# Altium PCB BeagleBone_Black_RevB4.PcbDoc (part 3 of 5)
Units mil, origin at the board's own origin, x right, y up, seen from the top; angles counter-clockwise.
Board outline 3401 x 2151 mil, 6 copper layers (TOP, LYR2_GND, LYR3, LYR4, LYR5_PWR, BOTTOM), stack 62 mil thick; 381 components, 310 nets, 1705 pads, 850 vias.
Unrouted connection lines stored in the file: 1.
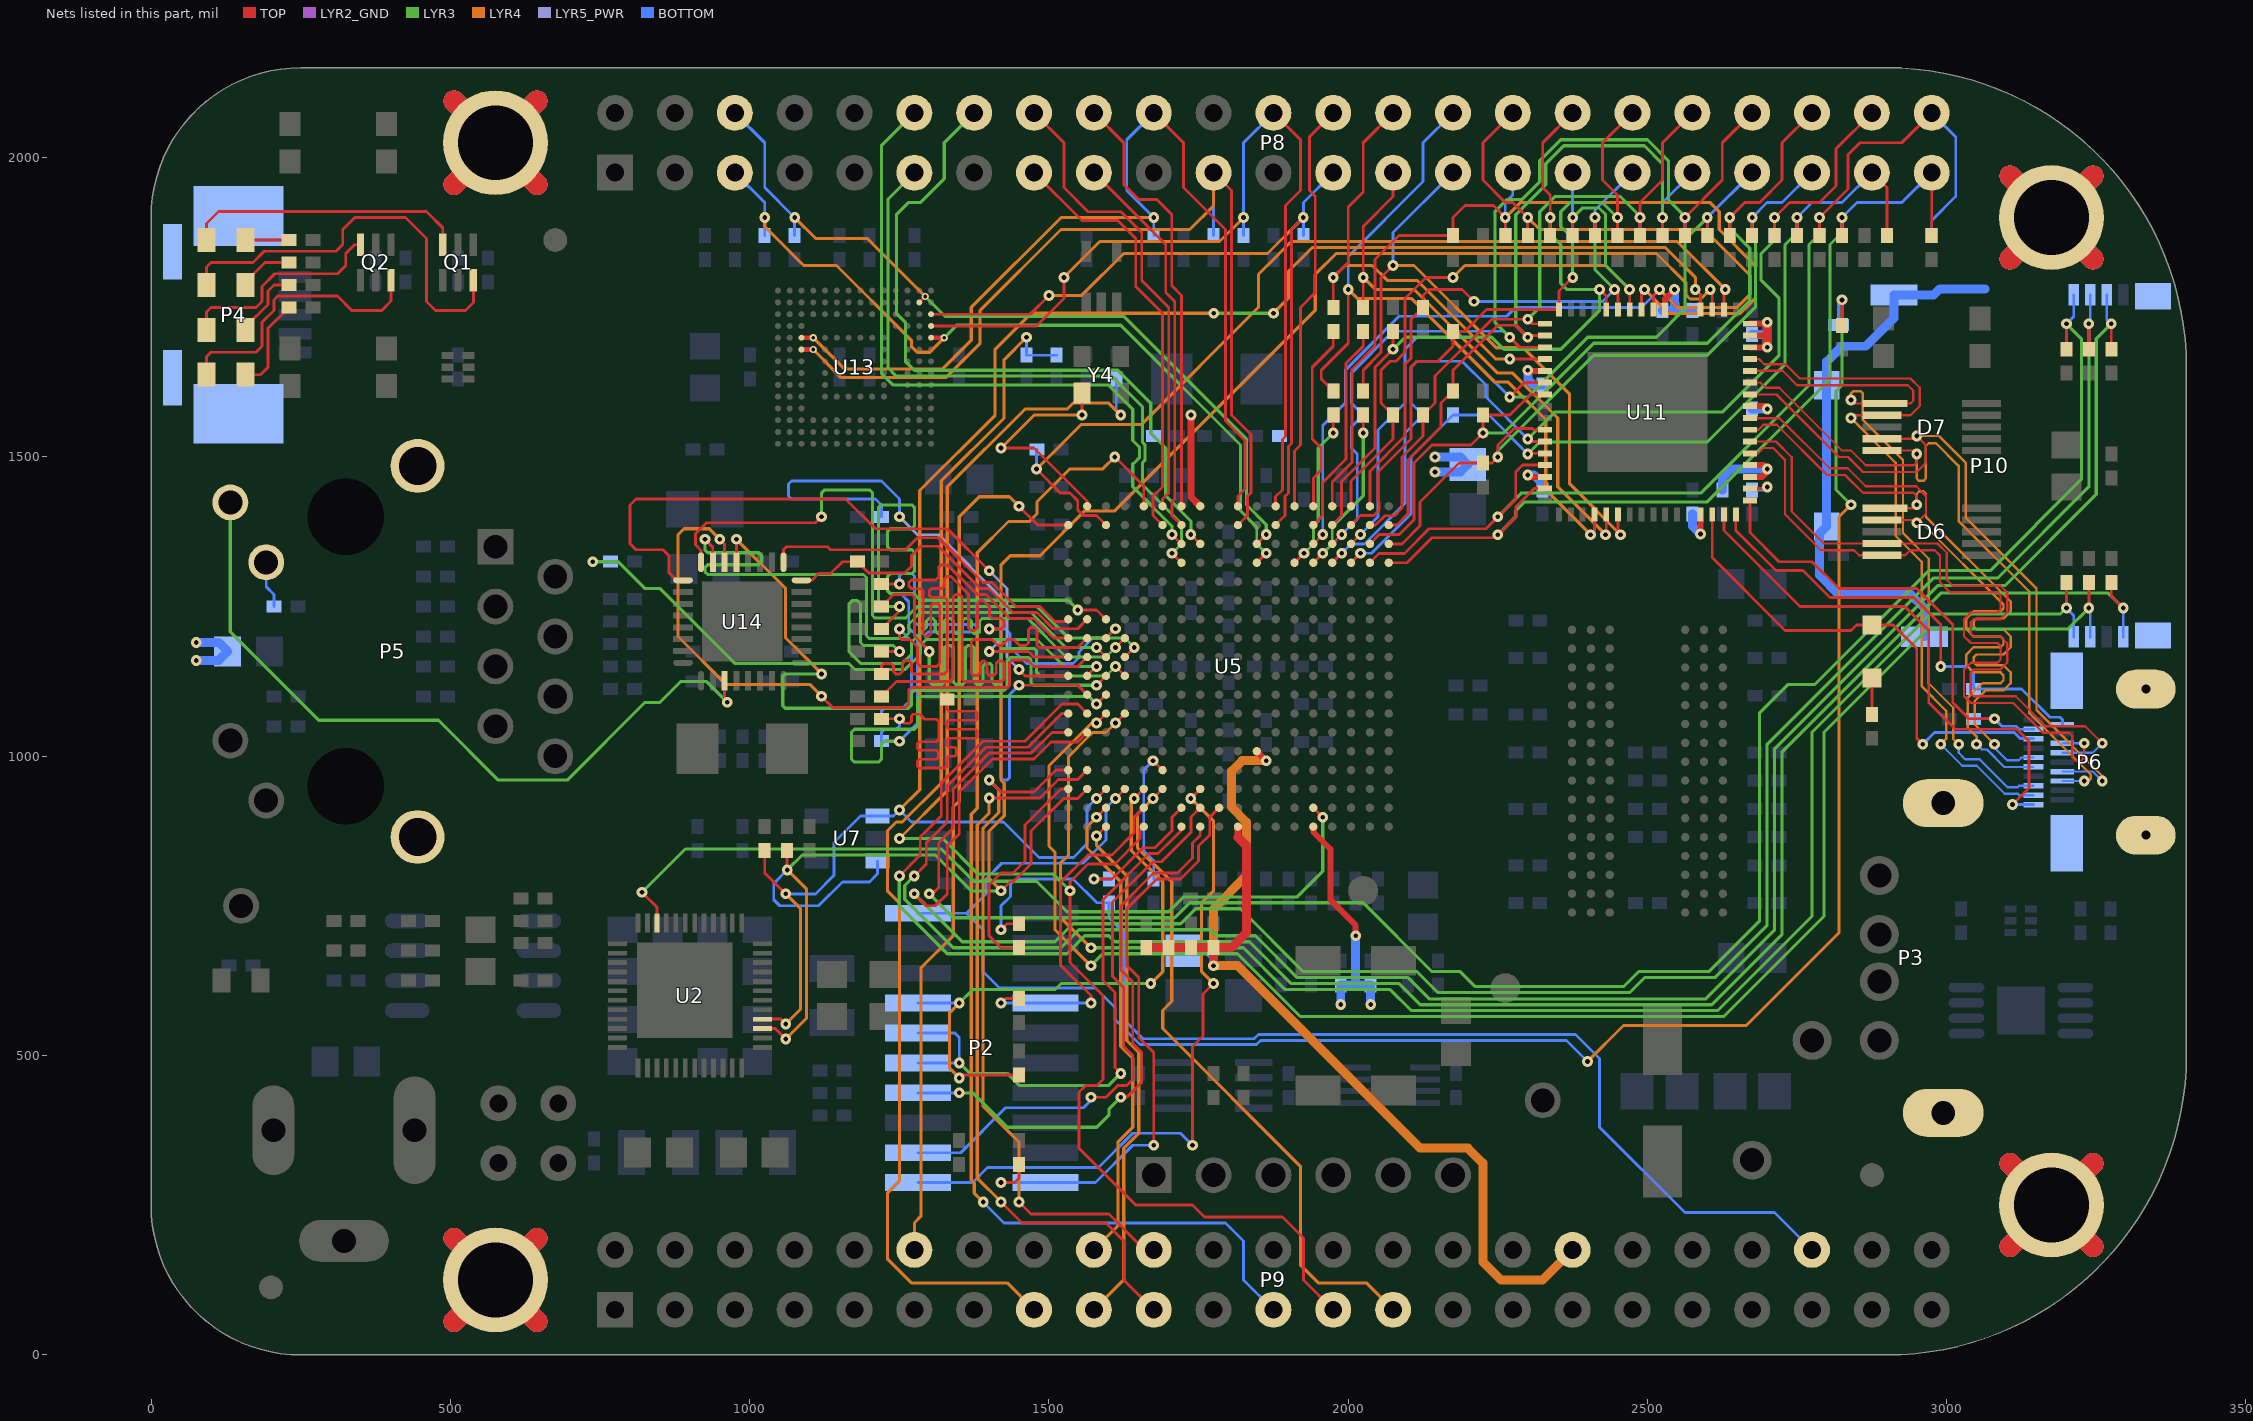
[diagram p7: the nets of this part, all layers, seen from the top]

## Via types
v1: diameter 18, hole 8, TOP to BOTTOM, tented both sides, 793 vias
v2: diameter 22, hole 12, TOP to BOTTOM, tented both sides, 30 vias
v3: diameter 12, hole 6, TOP to BOTTOM, tented both sides, 27 vias

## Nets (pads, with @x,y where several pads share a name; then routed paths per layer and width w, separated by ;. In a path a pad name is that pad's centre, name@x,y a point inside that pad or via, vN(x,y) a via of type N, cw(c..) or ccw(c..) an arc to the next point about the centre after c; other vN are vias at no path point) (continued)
GND_EARTH: MTG1.1 MTG2.1 MTG3.1 MTG4.1 P3.5 P3.6 P4.6 P4.7 P4.8 P4.9 P5.13 P5.14 P6.20 P6.21 P6.22 P6.23 P10.11 P10.12 P10.13 P10.14 P10.15 P10.16 R136.2 | length 7357.1
  TOP w35: 505.46,55.46 MTG1.1@575,125 ; 505.46,194.54 MTG1.1@575,125 ; 505.46,1955.46 MTG3.1@575,2025 ; 505.46,2094.54 MTG3.1@575,2025 ; 644.54,55.46 MTG1.1@575,125 ; 644.54,194.54 MTG1.1@575,125 ; 644.54,1955.46 MTG3.1@575,2025 ; 644.54,2094.54 MTG3.1@575,2025 ; 3105.46,180.46 MTG2.1@3175,250 ; 3105.46,319.54 MTG2.1@3175,250 ; 3105.46,1830.46 MTG4.1@3175,1900 ; 3105.46,1969.54 MTG4.1@3175,1900 ; 3244.54,180.46 MTG2.1@3175,250 ; 3244.54,319.54 MTG2.1@3175,250 ; 3244.54,1830.46 MTG4.1@3175,1900 ; 3244.54,1969.54 MTG4.1@3175,1900
  LYR2_GND w35: 505.46,55.46 MTG1.1@575,125 ; 505.46,194.54 MTG1.1@575,125 ; 505.46,1955.46 MTG3.1@575,2025 ; 505.46,2094.54 MTG3.1@575,2025 ; 644.54,55.46 MTG1.1@575,125 ; 644.54,194.54 MTG1.1@575,125 ; 644.54,1955.46 MTG3.1@575,2025 ; 644.54,2094.54 MTG3.1@575,2025 ; 3105.46,180.46 MTG2.1@3175,250 ; 3105.46,319.54 MTG2.1@3175,250 ; 3105.46,1830.46 MTG4.1@3175,1900 ; 3105.46,1969.54 MTG4.1@3175,1900 ; 3244.54,180.46 MTG2.1@3175,250 ; 3244.54,319.54 MTG2.1@3175,250 ; 3244.54,1830.46 MTG4.1@3175,1900 ; 3244.54,1969.54 MTG4.1@3175,1900
  LYR5_PWR w35: 505.46,55.46 MTG1.1@575,125 ; 505.46,194.54 MTG1.1@575,125 ; 505.46,1955.46 MTG3.1@575,2025 ; 505.46,2094.54 MTG3.1@575,2025 ; 644.54,55.46 MTG1.1@575,125 ; 644.54,194.54 MTG1.1@575,125 ; 644.54,1955.46 MTG3.1@575,2025 ; 644.54,2094.54 MTG3.1@575,2025 ; 3105.46,180.46 MTG2.1@3175,250 ; 3105.46,319.54 MTG2.1@3175,250 ; 3105.46,1830.46 MTG4.1@3175,1900 ; 3105.46,1969.54 MTG4.1@3175,1900 ; 3244.54,180.46 MTG2.1@3175,250 ; 3244.54,319.54 MTG2.1@3175,250 ; 3244.54,1830.46 MTG4.1@3175,1900 ; 3244.54,1969.54 MTG4.1@3175,1900
  BOTTOM w15: v1(75,1160) 112.5,1160 R136.2@127.5,1175 112.5,1190 v1(75,1190) ; P10.12@2963,1199.57 2963,1247 2940,1270 2820,1270 2787.5,1302.5 2787.5,1372.5 2798.63,1383.63 P10.16@2799.5,1383.63 P10.15@2799.5,1619.84 2799.5,1659.5 2825,1685 2864.66,1685 2911.82,1732.16 P10.11@2911.82,1770.43 2977.93,1770.43 2988.54,1781.04 3063.96,1781.04
  BOTTOM w35: 505.46,55.46 MTG1.1@575,125 ; 505.46,194.54 MTG1.1@575,125 ; 505.46,1955.46 MTG3.1@575,2025 ; 505.46,2094.54 MTG3.1@575,2025 ; 644.54,55.46 MTG1.1@575,125 ; 644.54,194.54 MTG1.1@575,125 ; 644.54,1955.46 MTG3.1@575,2025 ; 644.54,2094.54 MTG3.1@575,2025 ; 3105.46,180.46 MTG2.1@3175,250 ; 3105.46,319.54 MTG2.1@3175,250 ; 3105.46,1830.46 MTG4.1@3175,1900 ; 3105.46,1969.54 MTG4.1@3175,1900 ; 3244.54,180.46 MTG2.1@3175,250 ; 3244.54,319.54 MTG2.1@3175,250 ; 3244.54,1830.46 MTG4.1@3175,1900 ; 3244.54,1969.54 MTG4.1@3175,1900
GND_OSC0: C25.2 C26.2 U5.V11 | length 158.6
  TOP w12: v1(1737.5,1570) 1737.5,1432.98 U5.V11@1752.76,1417.72
GND_OSC1: C21.1 C22.1 U5.A5 | length 409.1
  TOP w10: U5.A5@1941.73,882.28 1941.73,873.27 1970,845 1970,760 2012.5,717.5 v1(2012.5,700)
  BOTTOM w15: v1(1987.5,585) C21.1@1987.5,617.5 2012.5,617.5 ; v1(2012.5,700) 2012.5,617.5 ; v1(2037.5,585) C22.1@2037.5,617.5 2012.5,617.5
GNDA_ADC: C31.2 C32.2 C33.2 C93.2 FB3.1 P9.34 U5.A9 U5.E8 | length 1840.7
  TOP w10: U5.E8@1847.24,1008.27 v1(1862.99,992.52)
  TOP w12: 1815.75,865 U5.A9@1815.75,882.28
  TOP w15: C32.2@1662.5,680 C31.2@1700,680 C33.2@1737.5,680 C93.2@1775,680 ; v1(1775,650) C93.2@1775,680 ; 1815.75,865 1815.75,864.25 1830,850 1830,705 1805,680 C93.2@1775,680
  LYR4 w15: v1(1862.99,992.52) 1822.52,992.52 1805,975 1805,915 1830,890 1830,800 1775,745 v1(1775,650) 1815,650 2120,345 2200,345 2225,320 2225,155 2255,125 2325,125 P9.34@2375,175
  BOTTOM w15: FB3.1@1725,674.9 1765.25,674.9 1775,665.15 v1(1775,650)
GPIO0_7: P9.42 R50.1 R51.1 | length 1889.3
  TOP w4.75: v1(1420,710) 1430,720 R50.1@1450,720
  BOTTOM w4.75: v1(1420,710) 1420,750 1435.74,765.74 1435.74,785.74 1445,795 1540,795 1580,755 R51.1@1600,755 1600,730 1625,705 1625,560 1657.25,527.75 1842.75,527.75 1850,535 2380,535 2420,495 2420,380 2562.5,237.5 2712.5,237.5 P9.42@2775,175
GPIO0_7SRC: R50.2 U5.C18 | length 377.1
  TOP w4.75: R50.2@1450,680 1420,680 1400,700 1400,785 1419.62,804.62 1439.62,804.62 1460,825 1460,885 1520.28,945.28 U5.C18@1532.28,945.28
GPIO0_26: P8.14 U5.T11 | length 1195.3
  TOP w4.75: v1(1737,1370.5) U5.T11@1752.76,1354.72
  LYR3 w5.25: P8.14@1375,2075 1325,2025 1325,1965 1285,1925 1265,1925 1245,1905 1245,1740 1260,1725 1260,1660 1275,1645 1615,1645 1670,1590 1670,1540 1695,1515 1695,1435 1737,1393 v1(1737,1370.5)
GPIO0_27: P8.17 U5.U12 | length 653
  TOP w4.75: P8.17@1575,1975 1695,1855 1695,1775 1710,1760 1710,1430 1705.63,1425.63 1705.63,1401.85 U5.U12@1721.26,1386.22
GPIO1_12: P8.12 U5.T12 | length 1171.6
  TOP w4.75: v1(1705.5,1370.5) U5.T12@1721.26,1354.72
  LYR3 w5.25: P8.12@1275,2075 1220,2020 1220,1640 1240,1620 1600,1620 1640,1580 1640,1527.61 1650.99,1516.62 1650.99,1498.38 1641.62,1489.01 1640,1489.01 1640,1450 1705.5,1384.5 v1(1705.5,1370.5)
GPIO1_13: P8.11 U5.R12 | length 1100.4
  TOP w4.75: v1(1705.5,1339) U5.R12@1721.26,1323.23
  LYR3 w4.75: v1(1705.5,1339) 1721.26,1354.76 1721.26,1388.74
  LYR3 w5.25: P8.11@1275,1975 1230.91,1930.91 1230.91,1649.09 1245,1635 1605,1635 1656.26,1583.74 1656.26,1524.44 1660.24,1520.46 1660.24,1494.54 1656.26,1490.56 1656.26,1453.74 1721.26,1388.74
GPIO1_14: P8.16 U5.V13 | length 786.9
  TOP w4.75: P8.16@1475,2075 1525,2025 1525,1950 1565.25,1909.75 1620.25,1909.75 1655,1875 1655,1795 1700,1750 1700,1440 1689.76,1429.76 U5.V13@1689.76,1417.72
GPIO1_15: P8.15 U5.U13 | length 725.9
  TOP w4.75: P8.15@1475,1975 1555,1895 1615,1895 1645,1865 1645,1785 1689.74,1740.26 1689.74,1450 1674.03,1434.29 1674.03,1401.95 U5.U13@1689.76,1386.22
GPIO1_16: P9.15 R160.2 R161.2 | length 2018.9
  LYR4 w5.25: v1(1462.5,1700) 1425,1662.5 1425,1565 1320,1460 1320,955 1255,890 1245,890 1230,875 1230,775 1250,755 1250,290 1230,270 1230,160 1270,120 1430,120 P9.15@1475,75
  BOTTOM w4.75: v1(1462.5,1700) R161.2@1462.5,1670 R160.2@1512.5,1670
GPIO1_17: P9.23 U5.V14 | length 2105.3
  TOP w4.75: v1(1610,1500) 1658.27,1451.73 U5.V14@1658.27,1417.72
  LYR4 w5.25: v1(1390,255) 1375,270 1375,286.91 1370,291.91 1370,903.09 1380,913.09 1380,1340 1432.26,1392.26 1467.26,1392.26 1480,1405 1480,1425 1535,1480 1590,1480 v1(1610,1500)
  BOTTOM w4.75: v1(1390,255) 1425,220 1795,220 1825,190 1825,125 P9.23@1875,75
GPIO1_28: P9.12 U5.U18 | length 1471.8
  TOP w4.75: v1(1450,1417.5) 1481.28,1386.22 U5.U18@1532.28,1386.22
  LYR4 w5.25: P9.12@1275,175 1275,220 1285.99,230.99 1285.99,645.99 1340,700 1340,915 1350,925 1350,1400 1383.49,1433.49 1434.01,1433.49 v1(1450,1417.5)
GPIO1_29: P8.26 U5.V6 | length 692.4
  TOP w4.75: U5.V6@1910.24,1417.72 1910.24,1510.24 1920,1520 1920,1750 1945,1775 1945,1935 1935,1945 1935,2035 P8.26@1975,2075
GPIO2_1: P8.18 U5.V12 | length 735.4
  TOP w4.75: P8.18@1575,2075 1625,2025 1625,1955 1650,1930 1680,1930 1705,1905 1705,1786.26 1721.26,1770 U5.V12@1721.26,1417.72
GPIO3_18: R51.2 U5.B12 | length 233.7
  TOP w4.75: v1(1575,795) 1605,795 1657.12,847.12 1677.12,847.12 1705.39,875.39 1705.39,897.91 U5.B12@1721.26,913.78
  BOTTOM w4.75: v1(1575,795) R51.2@1600,795
GPIO3_19: P9.27 U5.C13 | length 1123.9
  TOP w4.75: v1(1674,929.5) U5.C13@1689.76,945.28
  LYR4 w5.25: v1(1674,929.5) 1647.76,903.26 1647.76,847.24 1705,790 1705,590 1690,575 1690,545 1920,315 1920,150 1950,120 2030,120 P9.27@2075,75
GPIO3_20: R20.2 U5.D13 | length 233.2
  TOP w4.75: v1(1674,992.5) U5.D13@1689.73,976.77
  BOTTOM w4.75: v1(1674,992.5) 1658.26,976.76 1658.26,841.74 1675,825 R20.2@1675,795
GPIO3_21: P9.25 R167.2 U5.A14 | length 2603.7
  TOP w4.75: U5.A14@1658.27,882.28 1652.25,876.26 1652.25,862.25 1610,820 1565,820 1535,790 v1(1535,775) 1535,655 1590,600 1590,460 1580,450 1561.38,450 1550,438.62 1550,345 1645,250 1740,250 1760,230 1890,230 1925,195 1925,125 P9.25@1975,75
  LYR3 w5.25: v1(1250.25,862.5) 1322.5,862.5 1382,803 1507,803 v1(1535,775)
  LYR4 w5.25: v1(1250.25,862.5) 1330,942.25 1330,1450 1460,1580 1530,1580 1540,1590 1600,1590 v1(1620,1570)
  BOTTOM w4.75: R167.2@1612.5,1630 1612.5,1577.5 v1(1620,1570)
GRN_C: P5.10 R132.2 | length 79.4
  BOTTOM w4.75: P5.10@192,1324 192,1283 205,1270 R132.2@205,1250
GRNA: P5.9 U14.3 | length 1270
  TOP w4.75: U14.3@957.95,1126 957.95,1094.55 v1(962.5,1090)
  LYR3 w5.25: P5.9@132,1424 132,1208 280,1060 480,1060 580,960 695,960 825,1090 850,1090 885,1125 927.5,1125 v1(962.5,1090)
HDMI_1V8: C144.1 C145.1 C146.1 C147.1 C148.1 C149.1 C150.1 C151.1 FB5.1 U11.5 U11.14 U11.29 U11.35 U11.36 U11.41 U11.46 U11.47 U11.48 U11.55 | length 882.9
  TOP w10: v1(2300,1470) 2303.27,1466.73 U11.14@2328.74,1466.73 ; v1(2300,1645) 2301.1,1643.9 U11.5@2328.74,1643.9 ; U11.55@2529.53,1746.26 2529.53,1763.56 2545,1779.03 v1(2545,1780) ; v1(2588.58,1371.42) U11.29@2588.58,1403.74 ; U11.35@2671.26,1466.73 2691.73,1466.73 2700,1475 v1(2700,1480) 2693.58,1486.42 U11.36@2671.26,1486.42 ; U11.41@2671.26,1584.84 2695.16,1584.84 v1(2700,1580) ; U11.46@2671.26,1683.27 v1(2700,1683.27) ; U11.47@2671.26,1702.95 2700,1702.95 ; U11.48@2671.26,1722.64 2697.64,1722.64 v1(2700,1725)
  TOP w15: v1(2700,1683.27) 2700,1702.95 v1(2700,1725)
  BOTTOM w15: v1(2145,1475) 2187.6,1475 FB5.1@2200,1487.4 2187.4,1500 v1(2145,1500) ; v1(2300,1470) 2310,1470 2325,1455 C145.1@2325,1445 ; v1(2300,1645) 2300,1630 2310,1620 C144.1@2325,1620 ; C146.1@2525,1745 2545,1745 ; v1(2545,1780) 2545,1745 ; C147.1@2575,1405 2575,1385 v1(2588.58,1371.42) ; C148.1@2575,1745 2545,1745 ; C151.1@2625,1445 2625,1465 2640,1480 v1(2700,1480) ; C150.1@2675,1580 v1(2700,1580) ; C149.1@2675,1705 2700,1705 ; v1(2700,1683.27) 2700,1705 ; v1(2700,1725) 2700,1705
HDMI_CEC: D8.1 P6.15 U11.30 | length 845.7
  TOP w4.75: U11.30@2608.27,1403.74 2608.27,1331.73 2730,1210 2840,1210 2849.29,1219.29 D8.1@2875,1219.29 2910.71,1219.29 2950,1180 2950,1030 v1(2960,1020)
  BOTTOM w4.75: v1(2960,1020) 2979.37,1039.37 3112.89,1039.37 3122.89,1029.37 P6.15@3145.08,1029.37
HDMI_CEC_D: D8.2 R166.1 | length 60.7
  TOP w4.75: R166.1@2875,1070 D8.2@2875,1130.71
HDMI_DSCL: P6.17 R146.2 U11.33 | length 774.7
  TOP w4.75: U11.33@2671.26,1427.36 2671.26,1373.74 2720,1325 2775,1325 2820,1280 2950,1280 3010,1220 3010,1090 3037.5,1062.5 v1(3080,1062.5)
  BOTTOM w4.75: R146.2@3045,1062.5 v1(3080,1062.5) 3092.5,1050 3116.05,1050 3120.93,1045.12 P6.17@3145.08,1045.12
HDMI_DSDA: P6.18 R147.2 U11.32 | length 768.2
  TOP w4.75: U11.32@2647.64,1403.74 2647.64,1377.36 2715,1310 2760,1310 2805,1265 2945,1265 2990,1220 v1(2990,1150)
  BOTTOM w4.75: v1(2990,1150) 3035,1150 3045,1140 R147.2@3045,1112.5 3125.14,1112.5 3172.64,1065 3189.31,1065 3193.31,1061 P6.18@3193.31,1052.99
HDMI_HPD: P6.1 U11.31 | length 904.7
  TOP w4.75: U11.31@2627.95,1403.74 2627.95,1377.05 2755,1250 2930,1250 2970,1210 2970,1090 3015,1045 3117.5,1045 3137.5,1025 3137.5,946.63 v1(3110,919.13)
  BOTTOM w4.75: v1(3110,919.13) P6.1@3145.08,919.13
HDMI_INT: R158.2 U5.U16 U11.50 | length 1605.4
  TOP w4.75: v1(1479.16,1479.72) 1518.88,1440 1535,1440 1548.15,1426.85 1548.15,1411.25 1557.31,1402.09 1579.41,1402.09 U5.U16@1595.28,1386.22 ; U11.50@2627.95,1746.26 2627.95,1777.95 v1(2630,1780)
  LYR4 w5.25: v1(1479.16,1479.72) 1553.45,1554.01 1654.01,1554.01 1850,1750 1850,1805 1905,1860 2550,1860 v1(2630,1780)
  BOTTOM w4.75: v1(1479.16,1479.72) 1479.16,1511.66 R158.2@1480,1512.5
HDMI_SWING: R148.1 U11.34 | length 57
  TOP w4.75: U11.34@2671.26,1447.05 2697.05,1447.05 v1(2700,1450)
  BOTTOM w4.75: R148.1@2675,1445 2695,1445 v1(2700,1450)
HDMI_TX0+: D6.2 P6.9 U11.40 | length 1261.6
  TOP w3.75: U11.40@2671.26,1565.16 2671.66,1564.76 2720.8,1564.76 2804.56,1481 2834.56,1481 2864.56,1451 2949,1451 2965.24,1434.76 2965.24,1405.24 v1(2950,1390) 2945.31,1394.69 D6.2@2892,1394.69
  LYR4 w4: v1(2950,1390) 2958.31,1390 3095,1253.31 3095,1246.69 3090.31,1242 3045.02,1242 3033,1229.98 3033,1212.02 3045.02,1200 3090,1200 3095,1195 3095,1187 3090,1182 3045.02,1182 3033,1169.98 3033,1152.02 3045.02,1140 3090,1140 3095,1135 3095,1127 3090,1122 3060.02,1122 3035,1096.98 3035,1048.02 3050,1033.02 v1(3050,1020)
  BOTTOM w3.75: v1(3050,1020) 3059,1011 3067.44,1011 3096.31,982.13 P6.9@3145.08,982.13
HDMI_TX0-: D6.1 P6.11 U11.39 | length 1262.5
  TOP w3.75: U11.39@2671.26,1545.47 2685.47,1545.47 2693.76,1553.76 2716.24,1553.76 2800,1470 2830,1470 2860,1440 2944.44,1440 2950,1434.44 v1(2950,1420) 2944.37,1414.37 D6.1@2897,1414.37
  LYR4 w4: v1(2950,1420) 2950,1438.5 2954.5,1443 2960.86,1443 2965.36,1438.5 2965.36,1399.93 3107,1258.29 3107,1241.71 3095.29,1230 3050,1230 3045,1225 3045,1217 3050,1212 3094.98,1212 3107,1199.98 3107,1182.02 3094.98,1170 3050,1170 3045,1165 3045,1157 3050,1152 3094.98,1152 3107,1139.98 3107,1122.02 3094.98,1110 3065,1110 3047,1092 3047,1053 v1(3080,1020)
  BOTTOM w3.75: v1(3080,1020) 3079.65,1019.65 3079.65,1014.35 3100.87,993.13 3120.26,993.13 3125,997.87 P6.11@3145.08,997.87
HDMI_TX1+: D7.5 P6.6 U11.43 | length 1262.2
  TOP w3.75: U11.43@2671.26,1624.21 2688.85,1624.21 2697.53,1615.53 2720.03,1615.53 2824.56,1511 2839.56,1511 2864.56,1486 2945.44,1486 2950,1490.56 v1(2950,1505) 2944.37,1510.63 D7.5@2892,1510.63
  LYR4 w4: v1(2950,1505) 2950,1464 2954,1460 2961,1460 2965,1464 2965,1518 2970,1523 2982,1523 3020,1485 3020,1393.02 3138,1275.02 3138,1072 3241,969 3241,962.5 3237,958.5 v1(3230,958.5)
  BOTTOM w3.75: P6.6@3193.31,958.5 v1(3230,958.5)
HDMI_TX1-: D7.4 P6.8 U11.42 | length 1264.7
  TOP w3.75: U11.42@2671.26,1604.53 2715.47,1604.53 2820,1500 2835,1500 2860,1475 2950,1475 2965.24,1490.24 2965.24,1519.76 v1(2950,1535) 2945.31,1530.31 D7.4@2892,1530.31
  LYR4 w4: v1(2950,1535) 2986.98,1535 3032,1489.98 3032,1398 3150,1280 3150,1076.98 3260,966.98 v1(3260,958.5)
  BOTTOM w3.75: P6.8@3193.31,974.25 3244.25,974.25 v1(3260,958.5)
HDMI_TX2+: D7.2 P6.3 U11.45 | length 1262.4
  TOP w3.75: U11.45@2671.26,1663.58 2686.32,1663.58 2695,1654.9 2730.66,1654.9 2754.56,1631 2939.56,1631 2955,1615.56 2955,1585 2939.69,1569.69 D7.2@2892,1569.69 2844.69,1569.69 v1(2840,1565)
  LYR4 w4: v1(2840,1565) 2915,1490 2915,1368.02 2958,1325.02 2958,1117.02 2999,1076.02 2999,1029 v1(2990,1020)
  BOTTOM w3.75: v1(2990,1020) 3026,984 3050.44,984 3097.19,937.25 3118.82,937.25 3121.19,934.88 P6.3@3145.08,934.88
HDMI_TX2-: D7.1 P6.5 U11.44 | length 1262.4
  TOP w3.75: U11.44@2671.26,1643.9 2726.1,1643.9 2750,1620 2935,1620 2944,1611 2944,1594 2939.37,1589.37 D7.1@2897,1589.37 2845.63,1589.37 v1(2840,1595)
  LYR4 w4: v1(2840,1595) 2840,1606 2844,1610 2856,1610 2860,1606 2860,1561.98 2927,1494.98 2927,1373 2970,1330 2970,1122 3011,1081 3011,1029 v1(3020,1020)
  BOTTOM w3.75: v1(3020,1020) 3020,1005.56 3030.56,995 3055,995 3101.75,948.25 3118.82,948.25 3121.2,950.63 P6.5@3145.08,950.63
HDMI_TXC+: D6.4 P6.12 U11.38 | length 1264
  TOP w3.75: U11.38@2671.26,1525.79 2714.77,1525.79 2741,1499.56 2741,1409 2794.69,1355.31 D6.4@2892,1355.31 2984.56,1355.31 3000,1339.87 3000,1295 3010,1285 3089.56,1285 3101,1273.56 3101,1240.44 3089.56,1229 3045,1229 3040,1224 3040,1205 3045,1200 3089.56,1200 3101,1188.56 3101,1156.44 3089.56,1145 3045,1145 3040,1140 3040,1105 3045,1100 3115.56,1100 3165.56,1050 3231.5,1050 v1(3260,1021.5)
  BOTTOM w3.75: P6.12@3193.31,1005.75 3244.25,1005.75 v1(3260,1021.5)
HDMI_TXC-: D6.5 P6.14 U11.37 | length 1262.2
  TOP w3.75: U11.37@2671.26,1506.1 2685,1506.1 2693.69,1514.79 2710.21,1514.79 2730,1495 2730,1404.44 2790.13,1344.31 2845.03,1344.31 2853.71,1335.63 D6.5@2892,1335.63 2930.28,1335.63 2938.96,1344.31 2980,1344.31 2989,1335.31 2989,1290.44 3005.44,1274 3085,1274 3090,1269 3090,1245 3085,1240 3040.44,1240 3029,1228.56 3029,1200.44 3040.44,1189 3085,1189 3090,1184 3090,1161 3085,1156 3040.44,1156 3029,1144.56 3029,1100.44 3040.44,1089 3111,1089 3161,1039 3205,1039 3210,1034 3210,998 3215,993 3225,993 3230,998 v1(3230,1021.5)
  BOTTOM w3.75: P6.14@3193.31,1021.5 v1(3230,1021.5)
HDMICLK_DISN: U5.V17 Y4.1 | length 383.8
  TOP w4.75: v1(1420,1515) 1475,1515 1563.78,1426.22 U5.V17@1563.78,1417.72 ; v1(1555,1570) Y4.1@1555,1607
  LYR4 w5.25: v1(1420,1515) 1475,1570 v1(1555,1570)
I2C0_SCL: R3.2 U2.28 U5.C16 U7.1 U11.52 | length 3289.3
  TOP w4.75: U2.28@1021.06,560.63 1051.87,560.63 v1(1060,552.5) ; R3.2@1025,842.5 1025,805 v1(1060,770) ; v1(1579.5,929.5) U5.C16@1595.28,945.28 ; v1(2580,1780) 2588.58,1771.42 U11.52@2588.58,1746.26
  LYR3 w5.25: v1(1775.25,1740.25) v1(1875,1740.25)
  LYR4 w5.25: v1(1060,552.5) 1085,577.5 1085,745 v1(1060,770) ; v1(1250,910) 1284.01,944.01 1284.01,1444.01 1410,1570 1410,1680 1470.25,1740.25 v1(1775.25,1740.25) ; v1(1875,1740.25) 1900,1765.25 1900,1810 1940,1850 2530,1850 2580,1800 v1(2580,1780)
  BOTTOM w4.75: v1(1060,770) 1110,770 1140.95,800.95 1140.95,855.95 1185,900 U7.1@1213.5,900 1240,900 v1(1250,910) 1270,890 1423.95,890 1483.19,830.76 1540.76,830.76 1563.76,853.76 1563.76,913.76 v1(1579.5,929.5)
I2C0_SDA: R4.2 U2.27 U5.C17 U7.3 U11.51 | length 3395.3
  TOP w4.75: U2.27@1021.06,544.88 1042.62,544.88 v1(1060,527.5) ; v1(1062.5,810) R4.2@1062.5,842.5 ; v1(1420,775) 1435,790 1440,790 1470,820 1470,875 1524.55,929.55 1548.05,929.55 U5.C17@1563.78,945.28 ; v1(2605,1780) 2608.27,1776.73 U11.51@2608.27,1746.26
  LYR3 w5.25: v1(1062.5,810) 1087.5,835 1310,835 1370,775 v1(1420,775)
  LYR4 w5.25: v1(1060,527.5) 1095,562.5 1095,777.5 v1(1062.5,810) ; v1(1420,775) 1400,795 1400,875 1425.24,900.24 1425.24,954.76 1420,960 1420,1320 1435,1335 1485,1335 1560,1410 1610,1410 1945,1745 1945,1805 1980,1840 2515,1840 2564.01,1790.99 2564.01,1770.99 2570.99,1764.01 2589.01,1764.01 v1(2605,1780)
  BOTTOM w4.75: v1(1062.5,810) 1040,787.5 1040,760 1050,750 1115,750 1155,790 1200,790 1213.5,803.5 U7.3@1213.5,825
I2C1_SCL: P9.17 U5.A16 | length 874.1
  TOP w4.75: v1(1579.5,866.5) U5.A16@1595.28,882.28
  LYR4 w5.25: P9.17@1575,75 1625,125 1625,345 1650,370 1650,505 1630,525 1630,800 1579.5,850.5 v1(1579.5,866.5)
I2C1_SDA: P9.18 U5.B16 | length 810.5
  TOP w4.75: v1(1579.5,898) U5.B16@1595.28,913.78
  LYR4 w5.25: P9.18@1575,175 1615,215 1615,355 1640,380 1640,495 1620,515 1620,790 1563.51,846.49 1563.51,882.01 v1(1579.5,898)
I2C2_SCL: P9.19 U5.D17 | length 1250.6
  TOP w4.75: v1(1400,930) 1485,930 1516.01,961.01 1548.02,961.01 U5.D17@1563.78,976.77 ; v1(1420,255) 1455,220 1595,220 1625,190 1625,125 P9.19@1675,75
  LYR4 w5.25: v1(1400,930) 1400,905 1380,885 1380,295 v1(1420,255)
I2C2_SDA: P9.20 U5.D18 | length 1161.2
  TOP w4.75: v1(1400,960) 1420,940 1475,940 1511.77,976.77 U5.D18@1532.28,976.77 ; v1(1450,255) 1470,235 1600,235 1660,175 P9.20@1675,175
  LYR4 w5.25: v1(1400,960) 1415.99,944.01 1415.99,905.99 1390,880 1390,415 1450,355 v1(1450,255)
JTAG_EMU0: P2.13 R23.2 U5.C14 | length 1006.7
  TOP w4.75: v1(1350,462.5) 1355,467.5 R23.2@1450,467.5 ; v1(1642.5,929.5) U5.C14@1658.27,945.28
  LYR3 w5.25: v1(1350,587.5) 1372.5,610 1510,610 1520,620 v1(1670,620)
  LYR4 w5.25: v1(1350,462.5) 1334.01,478.49 1334.01,571.51 v1(1350,587.5) ; v1(1642.5,929.5) 1637.51,924.51 1637.51,842.49 1690,790 1690,640 v1(1670,620)
  BOTTOM w4.75: P2.13@1281,587.5 v1(1350,587.5)
JTAG_EMU1: P2.14 R24.2 U5.B14 | length 611.4
  TOP w4.75: v1(1420,587.5) 1427.5,595 R24.2@1450,595 ; v1(1570,587.5) 1570,600 1519.26,650.74 1519.26,789.26 1565,835 1605,835 1642.5,872.5 1642.5,898.01 U5.B14@1658.27,913.78
  BOTTOM w4.75: v1(1420,587.5) P2.14@1494,587.5 v1(1570,587.5)
JTAG_TCK: P2.9 P2.11 U5.A12 | length 965.3
  TOP w4.75: v1(1620,470) 1610,480 1610,605 1590,625 1590,760 1667.37,837.37 1682.26,837.37 1708.65,863.76 1708.76,863.76 1721.26,876.26 U5.A12@1721.26,882.28
  LYR3 w5.25: v1(1350,487.5) 1367.5,470 1430,470 1450,450 1600,450 v1(1620,470)
  BOTTOM w4.75: P2.9@1281,487.5 v1(1350,487.5) 1350,530 1342.5,537.5 P2.11@1281,537.5
JTAG_TDI: P2.3 U5.B11 | length 949.4
  TOP w4.75: v1(1570,430) 1595,430 1615,450 1630,450 1640,460 1640,500 1625,515 1625,613.75 1606.38,632.37 1606.38,756.38 1673.62,823.62 1687.96,823.62 1737.13,872.79 1737.13,898.15 U5.B11@1752.76,913.78
  BOTTOM w4.75: P2.3@1281,337.5 1352.5,337.5 1427.5,412.5 1557.5,412.5 1570,425 v1(1570,430)
JTAG_TDO: P2.7 U5.A11 | length 954.8
  TOP w4.75: v1(1620,430) 1630,430 1655,455 1655,505 1640,520 1640,622.5 1620.13,642.37 1620.13,750.13 1674.75,804.75 1674.99,805 1715,805 1740,830 1740,855 1752.76,867.76 U5.A11@1752.76,882.28
  LYR3 w5.25: v1(1350,437.5) 1372.5,437.5 1430,380 1580,380 1600,400 1600,410 v1(1620,430)
  BOTTOM w4.75: P2.7@1281,437.5 v1(1350,437.5)
JTAG_TMS: P2.1 U5.C11 | length 1150.1
  TOP w4.75: v1(1737,929.5) U5.C11@1752.76,945.28 ; v1(1740,350) 1740,515 1757.5,532.5 1757.5,602.5 v1(1775,620)
  LYR4 w5.25: v1(1737,929.5) 1775,891.5 1775,775 1755,755 1755,640 v1(1775,620)
  BOTTOM w4.75: P2.1@1281,287.5 1372.5,287.5 1397.5,312.5 1582.5,312.5 1640,370 1720,370 v1(1740,350)
JTAG_TRSTN: P2.2 R25.1 U5.B10 | length 1006.3
  TOP w4.75: v1(1420,287.5) 1442.5,287.5 1450,295 R25.1@1450,317.5 ; v1(1675,350) 1675,505 1650,530 1650,630 1630,650 1630,745.05 1679.95,795 1720,795 1750,825 1750,850 1768.52,868.52 1768.52,898.05 U5.B10@1784.25,913.78
  BOTTOM w4.75: v1(1420,287.5) P2.2@1494,287.5 1577.5,287.5 1640,350 v1(1675,350)
LCD_DATA0: C173.1 P8.45 R70.2 R95.1 U5.R1 U11.15 | length 1614.7
  TOP w4.75: U5.R1@2067.72,1323.23 2098.23,1323.23 2140,1365 2245,1365 v1(2250,1370) 2280,1400 2280,1416.21 2310.84,1447.05 U11.15@2328.74,1447.05 ; R95.1@2825,1870 v1(2825,1900) ; C173.1@2975,1870 P8.45@2975,1975
  LYR3 w5.25: v1(2250,1370) 2280,1400 2280,1410 2295,1425 2600,1425 2805,1630 2805,1855 2825,1875 v1(2825,1900)
  BOTTOM w4.75: R70.2@2825,1870 v1(2825,1900) 2850,1925 2925,1925 P8.45@2975,1975
LCD_DATA1: C171.1 P8.46 R69.2 R94.1 U5.R2 U11.13 | length 1876.9
  TOP w4.75: U5.R2@2036.22,1323.23 2036.22,1323.72 2051.46,1338.96 2093.96,1338.96 2135,1380 2230,1380 v1(2250,1400) 2280,1430 2280,1475 2291.42,1486.42 U11.13@2328.74,1486.42 ; R94.1@2787.5,1870 v1(2787.5,1900) 2835,1947.5 2835,2005 2855,2025 2925,2025 P8.46@2975,2075
  LYR3 w5.25: v1(2250,1400) 2290,1440 2590,1440 2770,1620 2770,1855 2787.5,1872.5 v1(2787.5,1900)
  BOTTOM w4.75: R69.2@2787.5,1870 v1(2787.5,1900) ; C171.1@2975,1870 2975,1895 3015,1935 3015,2035 P8.46@2975,2075
LCD_DATA2: C172.1 P8.43 R68.2 R75.1 R93.1 U5.R3 U11.12 | length 1586.1
  TOP w4.75: U5.R3@2004.72,1323.23 v1(2020.5,1339) ; v1(2300,1505) 2301.1,1506.1 U11.12@2328.74,1506.1 ; R93.1@2750,1870 v1(2750,1900) ; P8.43@2875,1975 2900,1950 R75.1@2900,1870
  LYR3 w5.25: v1(2300,1505) 2320,1525 2600,1525 2730,1655 2730,1855 2750,1875 v1(2750,1900)
  BOTTOM w4.75: v1(2020.5,1339) 2039,1339 2105,1405 2105,1500 C172.1@2175,1570 2235,1570 v1(2300,1505) ; R68.2@2750,1870 v1(2750,1900) 2775,1925 2825,1925 P8.43@2875,1975
LCD_DATA3: C170.1 P8.44 R67.2 R92.1 U5.R4 U11.11 | length 1767.5
  TOP w4.75: U5.R4@1973.23,1323.23 v1(1989,1339) ; v1(2300,1530) 2304.21,1525.79 U11.11@2328.74,1525.79 ; R92.1@2712.5,1870 v1(2712.5,1900) 2737.5,1925 2787.5,1925 2815,1952.5 2815,2015 P8.44@2875,2075
  LYR3 w5.25: v1(2300,1530) 2345,1575 2625,1575 2720,1670 2720,1765 2690,1795 2690,1840 2712.5,1862.5 v1(2712.5,1900)
  BOTTOM w4.75: v1(1989,1339) 2004.75,1354.75 2027.01,1354.75 2095,1422.74 2095,1540 C170.1@2125,1570 2105,1590 2105,1650 2115,1660 2190,1660 2230,1620 2230,1600 v1(2300,1530) ; R67.2@2712.5,1870 v1(2712.5,1900)
LCD_DATA4: C169.1 P8.41 R66.2 R91.1 U5.T1 U11.10 | length 1259.6
  TOP w4.75: U5.T1@2067.72,1354.72 2089.72,1354.72 2120,1385 2120,1425 2185,1490 C169.1@2225,1490 2240,1490 v1(2250,1500) 2250,1520 2277.5,1547.5 2307.97,1547.5 2310,1545.47 U11.10@2328.74,1545.47 ; R91.1@2675,1870 v1(2675,1900)
  LYR3 w5.25: v1(2250,1500) 2250,1510 2410,1670 2600,1670 2680.24,1750.24 2680.24,1875 2675,1880.24 v1(2675,1900)
  BOTTOM w4.75: R66.2@2675,1870 v1(2675,1900) 2700,1925 2725,1925 P8.41@2775,1975
LCD_DATA5: C163.1 P8.42 R65.2 R90.1 U5.T2 U11.7 | length 1466.2
  TOP w4.75: U5.T2@2036.22,1354.72 2051.85,1370.35 2085.35,1370.35 2110,1395 2110,1490 2140,1520 2205,1520 v1(2225,1540) C163.1@2225,1570 2270,1570 2304.53,1604.53 U11.7@2328.74,1604.53 ; R90.1@2637.5,1870 v1(2637.5,1900) 2662.5,1925 2687.5,1925 2725,1962.5 2725,2025 P8.42@2775,2075
  LYR3 w5.25: v1(2225,1540) 2260,1540 2410,1690 2600,1690 2670.99,1760.99 2670.99,1849.01 2637.5,1882.5 v1(2637.5,1900)
  BOTTOM w4.75: R65.2@2637.5,1870 v1(2637.5,1900)
LCD_DATA6: C162.1 P8.39 R64.2 R89.1 U5.T3 U11.6 | length 1343.8
  TOP w4.75: U5.T3@2004.72,1354.72 v1(2020.5,1370.5) ; v1(2270,1600) 2294.21,1624.21 U11.6@2328.74,1624.21 ; R89.1@2600,1870 v1(2600,1900)
  LYR3 w5.25: v1(2270,1600) 2300,1600 2400,1700 2515,1700 2562.5,1747.5 2562.5,1862.5 v1(2600,1900)
  BOTTOM w4.75: v1(2020.5,1370.5) 2050,1400 2050,1545 C162.1@2075,1570 2095,1590 2095,1680 2115,1700 2170,1700 v1(2270,1600) ; R64.2@2600,1870 v1(2600,1900) P8.39@2675,1975
LCD_DATA7: C161.1 P8.40 R63.2 R88.1 U5.T4 U11.3 | length 1670.1
  TOP w4.75: U5.T4@1973.23,1354.72 v1(1989,1370.5) ; v1(2270,1700) 2286.73,1683.27 U11.3@2328.74,1683.27 ; R88.1@2562.5,1870 v1(2562.5,1900) 2625,1962.5 2625,2025 P8.40@2675,2075
  LYR3 w5.25: v1(2270,1700) 2245,1725 2245,1910 2265,1930 2290,1930 2320,1960 2320,1995 2355,2030 2500,2030 2535,1995 2535,1930 2562.5,1902.5 v1(2562.5,1900)
  BOTTOM w4.75: v1(1989,1370.5) 2015,1396.5 2015,1505 2005,1515 2005,1550 C161.1@2025,1570 2005,1590 2005,1640 2075,1710 2260,1710 v1(2270,1700) ; R63.2@2562.5,1870 v1(2562.5,1900)
LCD_DATA8: C160.1 P8.37 R62.2 R87.1 U5.U1 U11.2 | length 1290
  TOP w4.75: U5.U1@2067.72,1386.22 2081.22,1386.22 2100,1405 2100,1495 2155,1550 2155,1590 C160.1@2175,1610 2175,1645 2250,1720 2280,1720 v1(2300,1700) 2302.95,1702.95 U11.2@2328.74,1702.95 ; R87.1@2525,1870 v1(2525,1900)
  LYR3 w5.25: v1(2300,1700) 2280,1720 2280,1905 2330,1955 2330,1990 2360,2020 2495,2020 2525,1990 v1(2525,1900)
  BOTTOM w4.75: R62.2@2525,1870 v1(2525,1900) 2525,1925 P8.37@2575,1975
LCD_DATA9: C157.1 P8.38 R61.2 R86.1 U5.U2 U11.1 | length 1188
  TOP w4.75: U5.U2@2036.22,1386.22 2045.62,1386.22 2061.25,1401.85 2076.85,1401.85 2090,1415 2090,1500 2125,1535 C157.1@2125,1570 2145,1590 2145,1635 2240,1730 v1(2300,1730) 2307.36,1722.64 U11.1@2328.74,1722.64 ; R86.1@2487.5,1870 v1(2487.5,1900) 2487.5,1925 2525,1962.5 2525,2025 P8.38@2575,2075
  LYR3 w5.25: v1(2300,1730) 2320,1750 2320,1910 2345,1935 2455,1935 2487.5,1902.5 v1(2487.5,1900)
  BOTTOM w4.75: R61.2@2487.5,1870 v1(2487.5,1900)
LCD_DATA10: C156.1 P8.36 R60.2 R85.1 U5.U3 U11.64 | length 1180.9
  TOP w4.75: U5.U3@2004.72,1386.22 2020.59,1402.09 2042.69,1402.09 2051.85,1411.25 2051.85,1424.19 2050,1426.04 2050,1475 2105,1530 2105,1650 2115,1660 2150,1660 2175,1685 C156.1@2175,1710 2195,1710 2231.26,1746.26 U11.64@2352.36,1746.26 2352.36,1777.36 v1(2375,1800) ; R85.1@2450,1870 v1(2450,1900) 2450,1937.5 2425,1962.5 2425,2025 P8.36@2475,2075
  LYR3 w5.25: v1(2375,1800) 2375,1865 2355,1885 2355,1910 2370,1925 2401.8,1925 2402.04,1925.24 2424.76,1925.24 v1(2450,1900)
  BOTTOM w4.75: R60.2@2450,1870 v1(2450,1900)
LCD_DATA11: C168.1 P8.34 R59.2 R84.1 U5.U4 U11.60 | length 1275
  TOP w4.75: U5.U4@1973.23,1386.22 1988.96,1401.95 1988.96,1458.96 2045,1515 2045,1650 v1(2075,1680) C168.1@2075,1710 ; R84.1@2337.5,1870 v1(2337.5,1900) 2337.5,1937.5 2325,1950 2325,2025 P8.34@2375,2075 ; v1(2420,1780) 2431.1,1768.9 U11.60@2431.1,1746.26
  LYR3 w5.25: v1(2075,1680) 2095,1700 2240,1700 2260,1680 2355,1680 2420,1745 v1(2420,1780) 2365,1780 2355,1790 2355,1855 2337.5,1872.5 v1(2337.5,1900)
  BOTTOM w4.75: R59.2@2337.5,1870 v1(2337.5,1900)
LCD_DATA12: C167.1 P8.35 R58.2 R83.1 U5.V2 U11.59 | length 1060.3
  TOP w4.75: U5.V2@2036.22,1417.72 2036.22,1476.22 2095,1535 2095,1655 2105,1665 2105,1730 C167.1@2125,1750 2125,1770 2135,1780 2190,1780 v1(2210,1760) ; R83.1@2412.5,1870 v1(2412.5,1900) ; v1(2445,1780) 2450.79,1774.21 U11.59@2450.79,1746.26
  LYR3 w5.25: v1(2412.5,1900) 2412.5,1812.5 v1(2445,1780)
  BOTTOM w4.75: v1(2210,1760) 2425,1760 v1(2445,1780) ; R58.2@2412.5,1870 v1(2412.5,1900) 2412.5,1912.5 P8.35@2475,1975
LCD_DATA13: C166.1 P8.33 R57.2 R82.1 U5.V3 U11.58 | length 1198.2
  TOP w4.75: U5.V3@2004.72,1417.72 2004.72,1459.72 2075,1530 C166.1@2075,1570 2055,1590 2055,1645 2070,1660 2080,1660 2095,1675 2095,1765 2130,1800 v1(2175,1800) ; R82.1@2375,1870 v1(2375,1900) ; v1(2470,1780) 2470.47,1779.53 U11.58@2470.47,1746.26
  LYR3 w5.25: v1(2375,1900) 2390.75,1915.75 2405.64,1915.75 2405.88,1915.99 2419.12,1915.99 2430,1905.11 2430,1820 v1(2470,1780)
  LYR4 w5.25: v1(2175,1800) 2195,1820 2430,1820 v1(2470,1780)
  BOTTOM w4.75: R57.2@2375,1870 v1(2375,1900) P8.33@2375,1975
LCD_DATA14: C165.1 P8.31 R56.2 R81.1 U5.V4 U11.57 | length 1654.2
  TOP w4.75: U5.V4@1973.23,1417.72 1973.23,1458.23 2006.27,1491.27 2006.27,1646.27 2045,1685 2045,1830 2085,1870 C165.1@2175,1870 2175,1900 2195,1920 2242.5,1920 v1(2262.5,1900) R81.1@2262.5,1870 ; U11.57@2490.16,1746.26 2490.16,1773.47 v1(2495,1780)
  LYR4 w5.25: v1(2262.5,1900) 2287.5,1925 2605,1925 2620,1910 2620,1880 2680.24,1819.76 2680.24,1765.24 2655,1740 2535,1740 v1(2495,1780)
  BOTTOM w4.75: R56.2@2262.5,1870 v1(2262.5,1900) 2262.5,1925 2275,1937.5 P8.31@2275,1975
LCD_DATA15: C164.1 P8.32 R55.2 R80.1 U5.T5 U11.56 | length 1841.2
  TOP w4.75: U5.T5@1941.73,1354.72 v1(1957.5,1370.5) ; P8.32@2275,2075 2225,2025 2225,1962.5 2262.5,1925 2275,1925 v1(2300,1900) R80.1@2300,1870 ; U11.56@2509.84,1746.26 2509.84,1769.84 v1(2520,1780)
  LYR4 w5.25: v1(2300,1900) 2320,1880 2595,1880 2670.99,1804.01 2670.99,1770.99 2650,1750 2550,1750 v1(2520,1780)
  BOTTOM w4.75: v1(1957.5,1370.5) 1957.5,1552.5 C164.1@1975,1570 1995,1590 1995,1645 2085,1735 2265,1735 2280,1750 2490,1750 v1(2520,1780) ; R55.2@2300,1870 v1(2300,1900)
LCD_DE: P8.30 R48.2 U11.20 | length 1244.5
  TOP w4.75: R48.2@1975,1610 1955,1630 1955,1645 2000,1690 v1(2000,1780) ; v1(2405,1370) 2411.42,1376.42 U11.20@2411.42,1403.74
  LYR4 w5.25: v1(2000,1780) 2015,1765 2105,1765 2245,1625 2267.61,1625 2285.99,1606.62 2330,1562.62 2330,1445 v1(2405,1370)
  BOTTOM w4.75: v1(2000,1780) 2000,1835 2125,1960 2125,2025 P8.30@2175,2075
LCD_HSYNC: P8.29 R47.2 U11.22 | length 1116.9
  TOP w4.75: R47.2@2025,1610 2025,1645 2055,1675 2055,1800 v1(2075,1820) ; U11.22@2450.79,1403.74 2450.79,1374.21 v1(2455,1370)
  LYR4 w5.25: v1(2075,1820) 2110,1820 2247.5,1682.5 2292.5,1682.5 2370,1605 2370,1455 v1(2455,1370)
  BOTTOM w4.75: v1(2075,1820) 2075,1875 P8.29@2175,1975
LCD_PCLK: P8.28 R45.2 U11.4 | length 793.2
  TOP w4.75: R45.2@1975,1750 v1(1975,1800) 2000,1825 2000,1917.5 2025,1942.5 2025,2025 P8.28@2075,2075 ; v1(2270,1663.58) U11.4@2328.74,1663.58
  LYR4 w5.25: v1(1975,1800) 1995,1820 2040,1820 2065,1795 2115,1795 2246.42,1663.58 v1(2270,1663.58)
LCD_VSYNC: P8.27 R46.2 U11.21 | length 930.4
  TOP w4.75: R46.2@2025,1750 v1(2025,1800) 2025,1885 2075,1935 P8.27@2075,1975 ; v1(2430,1370) 2431.1,1371.1 U11.21@2431.1,1403.74
  LYR4 w5.25: v1(2025,1800) 2045,1780 2110,1780 2250,1640 2275,1640 2350,1565 2350,1450 v1(2430,1370)
LCDDE: R48.1 U5.R6 | length 273.6
  TOP w4.75: U5.R6@1910.24,1323.23 v1(1926,1339) ; v1(1975,1540) R48.1@1975,1570
  LYR3 w4.75: v1(1926,1339) 1941.74,1354.74 1941.74,1385
  LYR3 w5.25: 1941.74,1385 1950,1393.26 1950,1515 v1(1975,1540)
LCDPCLK: R45.1 U5.V5 | length 318.5
  TOP w4.75: U5.V5@1941.73,1417.72 1941.73,1465 1955,1478.27 1955,1515 1940,1530 1940,1650 1975,1685 R45.1@1975,1710
LCDVHYNC: R47.1 U5.R5 | length 281.3
  TOP w4.75: U5.R5@1941.73,1323.23 v1(1957.5,1339) ; v1(2025,1540) R47.1@2025,1570
  LYR3 w4.75: v1(1957.5,1339) 1973.26,1354.76 1973.26,1383.26
  LYR3 w5.25: 1973.26,1383.26 2025,1435 v1(2025,1540)
LCDVSYNC: R46.1 U5.U5 | length 358.3
  TOP w4.75: U5.U5@1941.73,1386.22 1957.5,1401.99 1957.5,1457.5 1996.52,1496.52 1996.52,1656.52 2025,1685 R46.1@2025,1710
LDO_PGOOD: U2.46 U5.B5 | length 1413.5
  TOP w4.75: v1(820,772.5) 844.88,747.62 U2.46@844.88,721.06 ; U5.B5@1941.73,913.78 v1(1957.5,898)
  LYR3 w5.25: v1(820,772.5) 892.5,845 1320,845 1374.01,790.99 1479.01,790.99 1530,740 1700,740 1725,765 1915,765 1957.5,807.5 v1(1957.5,898)
LEDAA: D2.2 R72.2 | length 72.5
  TOP w4.75: D2.2@157.5,1862.5 R72.2@230,1862.5
LEDAC: D2.1 Q1.6 | length 469.9
  TOP w4.75: D2.1@92.5,1862.5 92.5,1890 112.5,1910 460,1910 486.91,1883.09 Q1.6@486.91,1854.53
LEDBA: D3.2 R73.2 | length 91
  TOP w4.75: D3.2@157.5,1787.5 157.5,1792.5 190,1825 R73.2@230,1825
LEDBC: D3.1 Q1.3 | length 692.9
  TOP w4.75: D3.1@92.5,1787.5 92.5,1817.5 100,1825 170,1825 188.73,1843.73 308.73,1843.73 320,1855 320,1880 340,1900 425,1900 460,1865 460,1760 475,1745 525,1745 538.09,1758.09 Q1.3@538.09,1795.47
LEDCA: D4.2 R74.2 | length 119.7
  TOP w4.75: D4.2@157.5,1712.5 157.5,1717.5 195,1755 195,1777.5 205,1787.5 R74.2@230,1787.5
LEDCC: D4.1 Q2.6 | length 359.7
  TOP w4.75: D4.1@92.5,1712.5 92.5,1742.5 100,1750 175,1750 185,1760 185,1785 206.23,1806.23 311.23,1806.23 325,1820 325,1840 339.53,1854.53 Q2.6@349.41,1854.53
LEDDA: D5.2 R71.2 | length 157.2
  TOP w4.75: D5.2@157.5,1637.5 182.5,1637.5 195,1650 195,1715 R71.2@230,1750
LEDDC: D5.1 Q2.3 | length 464.9
  TOP w4.75: D5.1@92.5,1637.5 92.5,1667.5 100,1675 175,1675 185,1685 185,1725 205,1745 205,1762.5 211.23,1768.73 311.27,1768.73 335,1745 385,1745 400.59,1760.59 Q2.3@400.59,1795.47
MDIO_CLK: U5.M18 U14.17 | length 569
  TOP w4.75: U14.17@1056.45,1324 1056.45,1345.33 1061.12,1350 1130,1350 1135,1345 1260,1345 1280,1365 1315,1365 1390,1290 1405,1290 1445,1250 1485,1250 1510,1225 1528.54,1225 U5.M18@1532.28,1228.74
MDIO_DATA: R119.2 U5.M17 U14.16 | length 590.2
  TOP w4.75: U14.16@1086.5,1293.95 1103.95,1293.95 1115,1305 1135,1305 1155,1325 R119.2@1180,1325 1198.77,1306.23 1258.77,1306.23 1270,1317.46 1270,1335 1285.74,1350.74 1314.26,1350.74 1385,1280 1400,1280 1440,1240 1480,1240 1506.99,1213.01 1548.05,1213.01 U5.M17@1563.78,1228.74
MII1_COL: R138.1 U5.H16 | length 953.9
  TOP w4.75: v1(1579.5,1087.01) U5.H16@1595.28,1102.76
  LYR3 w5.25: v1(1250,1025) 1225,1025 1220,1020 1220,995 1215,990 1175,990 1170,995 1170,1040 1175,1045 1275,1045 1280,1050 1280,1095 1285,1100 1566.51,1100 v1(1579.5,1087.01)
  BOTTOM w4.75: R138.1@1220,1287.5 1237.5,1270 1253.71,1270 1265.74,1257.97 1265.74,1214.26 1280,1200 1280,1055 v1(1250,1025)
MII1_CRS_DV: R139.1 U5.H17 | length 1007.7
  TOP w4.75: R139.1@1220,1287.5 v1(1250,1287.5) ; v1(1450,1118.52) 1548.02,1118.52 U5.H17@1563.78,1102.76
  BOTTOM w4.75: v1(1250,1287.5) 1250,1301 1254,1305 1271.49,1305 1275.49,1301 1275.49,1224 1279.49,1220 1376,1220 1380,1216 1380,1211.5 1376,1207.5 1297.75,1207.5 1293.75,1203.5 1293.75,1199 1297.75,1195 1410,1195 1420,1185 1420,964 1424,960 1430.26,960 1434.26,964 1434.26,1102.78 v1(1450,1118.52)
MII1_REFCLK: R28.2 R124.1 R140.1 | length 719.8
  TOP w4.75: R124.1@1220,1062.5 v1(1250,1062.5) 1257.5,1055 1267,1055 1270,1058 1270,1067 1273,1070 1284.24,1070 1292.48,1061.76 1311.74,1061.76 1315.74,1057.76 1315.74,1028.26 1311.74,1024.26 1283,1024.26 1280,1021.26 1280,1013 1283,1010 1312,1010 1315,1007 1315,998 1312,995 1283,995 1280,992 1280,983 1283,980 1327,980 1330,983 1330,997 1333,1000 1342,1000 1345,1003 1345,1012 1342,1015 1333,1015 1330,1018 1330,1027 1333,1030 1377,1030 1380,1033 1380,1042 1377,1045 1333,1045 1330,1048 1330,1057 1333,1060 1377,1060 1380,1063 1380,1072 1377,1075 1333,1075 1330,1078 R28.2@1330,1095
  BOTTOM w4.75: R140.1@1220,1025 1220,1040 1225,1045 1245,1045 1250,1050 v1(1250,1062.5)
MII1_RXCLK: R131.1 U5.L18 | length 937.6
  TOP w4.75: v1(1250,1212.5) 1250,1199 1254,1195 1267.5,1195 1280,1182.5 1280,1155 1285,1150 1312.5,1150 1317.5,1155 1317.5,1251 1313.5,1255 1306.5,1255 1302.5,1251 1302.5,1204 1298.5,1200 1294,1200 1290,1204 1290,1275.75 1286,1279.75 1270.74,1279.75 1265.74,1284.75 1265.74,1290 1270,1294.26 1310.74,1294.26 1315.74,1299.26 1315.74,1315.74 1320,1320 1330,1320 1380,1270 1395,1270 1435,1230 1475,1230 1507.76,1197.24 U5.L18@1532.28,1197.24
  BOTTOM w4.75: R131.1@1220,1062.5 1220,1075 1225,1080 1255,1080 1270,1095 1270,1192.5 v1(1250,1212.5)
MII1_RXD0: R128.1 U5.M16 | length 955.6
  TOP w4.75: R128.1@1220,1212.5 1250,1242.5 v1(1250,1250) ; v1(1548,1244.5) 1579.5,1244.5 U5.M16@1595.28,1228.74
  LYR3 w5.25: v1(1250,1250) 1219,1250 1215,1254 1215,1416 1219,1420 1271,1420 1275,1416 1275,1384 1271,1380 1235,1380 1230,1375 1230,1350 1235,1345 1271,1345 1275,1341 1275,1309 1271,1305 1235,1305 1230,1300 1230,1276.51 1235,1271.51 1273.98,1271.51 1285,1260.49 1532.01,1260.49 v1(1548,1244.5)
MII1_RXD1: R127.1 U5.L15 | length 950.4
  TOP w4.75: R127.1@1220,1175 v1(1250,1175) ; v1(1611,1181.5) U5.L15@1626.74,1197.24
  LYR3 w4.75: 1565,1165.75 1595.25,1165.75 v1(1611,1181.5)
  LYR3 w5.25: v1(1250,1175) 1240,1185 1190,1185 1185,1190 1185,1255 1180,1260 1170.99,1260 1165.99,1255 1165.99,1174.01 1185,1155 1255,1155 1270,1170 1270,1190 1295,1215 1295,1226 1299,1230 1306,1230 1310,1226 1310,1209 1314,1205 1321,1205 1325,1209 1325,1226 1329,1230 1336,1230 1340,1226 1340,1209 1344,1205 1351,1205 1355,1209 1355,1226 1359,1230 1366,1230 1370,1226 1370,1209 1374,1205 1381,1205 1384.01,1208.01 1384.01,1226 1388.01,1230 1464.25,1230 1528.5,1165.75 1565,1165.75
MII1_RXD2: R126.1 U5.L16 | length 950.2
  TOP w4.75: R126.1@1220,1137.5 1220,1151 1224,1155 1236,1155 1240,1151 1240,1141.5 1244,1137.5 1251,1137.5 1255,1141.5 1255,1156 1259,1160 1266,1160 1270,1156 1270,1141.5 1274,1137.5 1325,1137.5 1330,1142.5 1330,1261 1326,1265 1304,1265 1300,1269 1300,1276 1304,1280 1321,1280 1325,1284 1325,1296 1329,1300 1336.21,1300 1365.6,1270.61 1365.6,1214.43 1370.03,1210 1376.28,1210 1380.71,1214.43 1380.71,1256.25 1384.71,1260.25 1390,1260.25 1400.6,1249.65 1400.6,1234.61 1404.6,1230.61 1420,1230.61 1425,1225.61 1425,1217.5 1420,1212.5 v1(1400,1212.5) ; U5.L16@1595.28,1197.28 v1(1611,1213)
  BOTTOM w4.75: v1(1400,1212.5) 1427.5,1212.5 1435,1205 1435,1182.26 1462.26,1155 1540,1155 1550,1165 1550,1174.26 1572.98,1197.24 1595.24,1197.24 v1(1611,1213)
MII1_RXD3: R125.1 U5.L17 | length 960.9
  TOP w4.75: R125.1@1220,1100 1245,1125 1335,1125 1340,1130 1340,1266 1344,1270 1351,1270 1355,1266 1355,1129 1359,1125 1421,1125 1424.51,1128.51 1424.51,1155.75 1421,1159.26 1415.74,1159.26 1411.74,1155.26 1411.74,1139 1407.74,1135 1400.26,1135 1396.26,1139 1396.26,1155.26 1392.26,1159.26 1389,1159.26 1385,1155.26 1385,1139 1381,1135 1374,1135 1370,1139 1370,1191 1374,1195 1405,1195 1415,1185 1421,1185 1431,1195 1441,1195 1451,1185 1461.74,1185 1465.74,1189 1465.74,1211.74 1469,1215 1476,1215 1480,1211 1480,1185.5 1484,1181.5 1548.04,1181.5 U5.L17@1563.78,1197.24
MII1_RXDV: R129.1 U5.J17 | length 1017
  TOP w4.75: U5.J17@1563.78,1134.25 v1(1579.5,1150.01)
  LYR3 w5.25: v1(737.5,1325) 780,1325 824.51,1280.49 849.51,1280.49 975,1155 1165,1155 1175,1145 1260,1145 1284.01,1169.01 1284.01,1184.01 1295,1195 1480,1195 1524.99,1150.01 v1(1579.5,1150.01)
  BOTTOM w4.75: v1(737.5,1325) R129.1@767.5,1325
MII1_RXERR: R133.1 U5.J15 | length 955
  TOP w4.75: R133.1@1220,1250 1240,1270 1271.25,1270 1275.25,1266 1275.25,1201.04 1300,1176.29 v1(1300,1175) ; v1(1611,1150) U5.J15@1626.75,1134.25
  LYR3 w4.75: 1569.27,1134.27 1595.27,1134.27 v1(1611,1150)
  LYR3 w5.25: v1(1300,1175) 1300,1125 1305,1120 1321,1120 1325,1124 1325,1181 1329,1185 1336,1185 1340,1181 1340,1124 1344,1120 1356,1120 1360,1124 1360,1181 1364,1185 1371,1185 1375,1181 1375,1124 1379,1120 1386,1120 1390,1124 1390,1151 1394,1155 1401,1155 1405,1151 1405,1124 1409,1120 1415,1120 1420,1125 1420,1176 1424,1180 1475.25,1180 1479.25,1176 1479.25,1140 1484.98,1134.27 1569.27,1134.27
MII1_TXCLK: R134.1 U5.K18 | length 891
  TOP w4.75: v1(1400,1175) 1465.75,1175 1475,1165.75 U5.K18@1532.28,1165.75
  LYR5_PWR w4.75: v1(1250,1400) 1280,1370 1315,1370 1420,1265 1420,1195 v1(1400,1175)
  BOTTOM w4.75: R134.1@1220,1400 1220,1420 1210,1430 1070,1430 1065,1435 1065,1455 1070,1460 1220,1460 1250,1430 v1(1250,1400)
MII1_TXD0: U5.K17 U14.22 | length 1106.5
  TOP w4.75: v1(950,1362.5) 957.95,1354.55 U14.22@957.95,1324 ; v1(1120,1100) 1138.77,1081.23 1260,1081.23 1265.74,1086.97 1265.74,1110.74 1270,1115 1431,1115 1434.26,1118.26 1434.26,1156.74 1438.26,1160.74 1464.28,1160.74 1475,1150.02 1548.05,1150.02 U5.K17@1563.78,1165.75
  LYR4 w5.25: v1(950,1362.5) 932.5,1380 890,1380 880,1370 880,1200 960,1120 1100,1120 v1(1120,1100)
MII1_TXD1: U5.K16 U14.23 | length 1107.6
  TOP w4.75: v1(925,1362.5) 938.25,1349.25 U14.23@938.25,1324 ; v1(1579.5,1181.5) U5.K16@1595.28,1165.75
  LYR3 w5.25: v1(925,1362.5) 925,1345 930,1340 1015,1340 1020,1335 1020,1325 1015,1320 929.84,1320 925,1315.16 925,1308.33 929.84,1303.49 1190,1303.49 1195,1298.49 1195,1201.51 1200,1196.51 1256.62,1196.51 1265.99,1205.88 1265.99,1220.99 1285,1240 1470,1240 1528.5,1181.5 v1(1579.5,1181.5)
MII1_TXD2: U5.K15 U14.24 | length 1105.7
  TOP w4.75: U14.24@918.55,1324 918.55,1343.95 909.26,1353.24 909.26,1371.76 927.5,1390 1110,1390 v1(1120,1400) ; U5.K15@1626.74,1165.75 v1(1642.5,1181.51)
  LYR3 w4.75: 1570,1197.24 1626.72,1197.24 v1(1642.5,1181.51)
  LYR3 w5.25: v1(1120,1400) 1120,1440 1125,1445 1200,1445 1205,1440 1205,1235.15 1209,1231.15 1261.15,1231.15 1280,1250 1480,1250 1532.76,1197.24 1570,1197.24
MII1_TXD3: U5.J18 U14.25 | length 1122.4
  TOP w4.75: U14.25@888.5,1293.95 877.5,1293.95 865,1306.45 865,1335 855,1345 810,1345 800,1355 800,1420 810,1430 1160,1430 1210,1380 1330,1380 v1(1400,1310) ; v1(1450,1145) 1450,1144 1459.75,1134.25 U5.J18@1532.28,1134.25
  LYR5_PWR w4.75: v1(1400,1310) 1430,1280 1430,1165 v1(1450,1145)
MII1_TXEN: U5.J16 U14.21 | length 1102.2
  TOP w4.75: U14.21@977.65,1324 v1(977.65,1362.5) ; v1(1579.5,1118.5) U5.J16@1595.28,1134.25
  LYR3 w5.25: v1(1120,1137.5) 1059,1137.5 1055,1133.5 1055,1084 1059,1080 1265,1080 1270,1085 1270,1105 1275,1110 1425,1110 1430,1115 1430,1160 1435,1165 1466,1165 1470,1161 1470,1122.5 1474,1118.5 v1(1579.5,1118.5)
  LYR4 w5.25: v1(977.65,1362.5) 1060,1280.15 1060,1197.5 v1(1120,1137.5)
MMC0_CD: P2.19 P10.10 R157.1 U5.C15 | length 3353
  TOP w4.75: v1(1611,929.5) U5.C15@1626.77,945.28 ; R157.1@2825,1720 v1(2825,1762.5)
  LYR3 w5.25: v1(2825,1762.5) 2825,1620 2815,1610 2815,1445 v1(2840,1420)
  LYR4 w5.25: v1(2400,490) 2460,550 2665,550 2820,705 2820,1400 v1(2840,1420)
  BOTTOM w4.75: P2.19@1281,737.5 1362.5,737.5 ; v1(1611,929.5) 1595.24,913.74 1595.24,859.98 1556.27,821.01 1421.01,821.01 1394.51,794.51 1394.51,769.51 1362.5,737.5 ; v1(2400,490) 2365,525 1853.79,525 1846.79,518 1652,518 1610,560 1610,580 1577.5,612.5 1417.5,612.5 1390,640 1390,710 1362.5,737.5 ; P10.10@2819.13,1720.24 2819.13,1756.63 v1(2825,1762.5)
MMC0_CLKO: P10.5 R152.2 U5.G17 | length 3250.5
  TOP w4.75: v1(1250,800) 1285,835 1285,865 1320,900 1320,955 1390,1025 1460,1025 1521.99,1086.99 1548.05,1086.99 U5.G17@1563.78,1071.26 ; R152.2@3275,1290 3275,1267.59 v1(3295.09,1247.5)
  LYR3 w5.25: v1(1250,800) 1249.76,799.76 1249.76,750.24 1330,670 1530,670 1560,700 1600,700 1610,690 1835,690 1905,620 2085,620 2120.24,584.76 2607.26,584.76 2725,702.5 2725,1007.5 2990,1272.5 3270.09,1272.5 v1(3295.09,1247.5)
  BOTTOM w4.75: P10.5@3295.09,1199.28 v1(3295.09,1247.5)
MMC0_CMD: P10.3 R151.2 U5.G18 | length 3471.7
  TOP w4.75: v1(1275,800) 1295,820 1295,855 1330,890 1330,950 1395,1015 1465,1015 1521.26,1071.26 U5.G18@1532.28,1071.26 ; R151.2@3275,1680 v1(3275,1722.5)
  LYR3 w5.25: v1(1275,800) 1259.01,784.01 1259.01,760.99 1340,680 1520,680 1550,710 1770,710 1780,700 1845,700 1915,630 2100,630 2135.99,594.01 2596.51,594.01 2712.5,710 2712.5,1012.5 2985,1285 3097.5,1285 3250,1437.5 3250,1697.5 v1(3275,1722.5)
  BOTTOM w4.75: P10.3@3267.53,1770.72 3267.53,1729.97 v1(3275,1722.5)
MMC0_DAT0: P10.7 R153.2 U5.G16 | length 2768.2
  TOP w4.75: v1(1579.5,1055.5) U5.G16@1595.28,1071.26 ; v1(3237.5,1247.5) R153.2@3237.5,1290
  LYR3 w5.25: v1(1570,650) 1590,670 1815,670 1920,565 2627.5,565 2795,732.5 2795,1040 2967.5,1212.5 3202.5,1212.5 v1(3237.5,1247.5)
  LYR4 w5.25: v1(1570,650) 1510,710 1510,726.91 1509.76,727.15 1509.76,840 1500,849.76 1500,983.88 1571.62,1055.5 v1(1579.5,1055.5)
  BOTTOM w4.75: v1(3237.5,1247.5) 3239.97,1245.03 P10.7@3239.97,1199.28
MMC0_DAT1: P10.8 R154.2 U5.G15 | length 2698.1
  TOP w4.75: v1(1611,1055.5) U5.G15@1626.77,1071.26 ; v1(3200,1247.5) R154.2@3200,1290
  LYR3 w5.25: v1(1570,680) 1825,680 1895,610 2070,610 2105,575 2617.5,575 2775,732.5 2775,1040 2972.5,1237.5 3190,1237.5 v1(3200,1247.5)
  LYR4 w4.75: 1564.43,1031.19 1573,1039.76 1595.26,1039.76 v1(1611,1055.5)
  LYR4 w5.25: 1564.43,1031.19 1532.76,999.52 1532.76,835 1519.01,821.25 1519.01,730.99 v1(1570,680)
  BOTTOM w4.75: v1(3200,1247.5) 3212.41,1235.09 P10.8@3212.41,1199.28
MMC0_DAT2: P10.1 R150.2 U5.F18 | length 3356.8
  TOP w4.75: v1(1300,770) 1305,770 1315.74,780.74 1315.74,855.74 1340,880 1340,945 1400.24,1005.24 1470.24,1005.24 1504.76,1039.76 U5.F18@1532.28,1039.76 ; R150.2@3200,1680 v1(3200,1722.5)
  LYR3 w5.25: v1(1300,770) 1340,730 1710,730 1735,755 2025,755 2140,640 2187.39,640 2212.39,615 2460,615 2485,640 2602.5,640 2687.5,725 2687.5,1072.5 2735,1120 2780,1120 2970,1310 3072.5,1310 3225,1462.5 3225,1697.5 v1(3200,1722.5)
  BOTTOM w4.75: v1(3200,1722.5) 3212.41,1734.91 P10.1@3212.41,1770.72
MMC0_DAT3: P10.2 R155.2 U5.F17 | length 3472.8
  TOP w4.75: v1(1275,770) 1295,750 1310,750 1330,770 1330,850 1350,870 1350,940 1405.49,995.49 1475,995.49 1503.41,1023.9 1547.92,1023.9 U5.F17@1563.78,1039.76 ; R155.2@3237.5,1680 v1(3237.5,1722.5)
  LYR3 w5.25: v1(1275,770) 1355,690 1510,690 1540,720 1720,720 1745,745 1820,745 1925,640 2115,640 2150,605 2470,605 2495,630 2612.5,630 2700,717.5 2700,1020 2977.5,1297.5 3085,1297.5 3237.5,1450 v1(3237.5,1722.5)
  BOTTOM w4.75: v1(3237.5,1722.5) 3239.97,1724.97 P10.2@3239.97,1770.72
MMC1_CLK: P8.21 R110.2 U5.U9 U13.M6 | length 1643
  TOP w4.75: P8.21@1775,1975 1805,1945 1805,1570 1837.49,1537.51 1837.49,1440.23 1831.48,1434.22 1831.48,1401.95 U5.U9@1815.75,1386.22
  TOP w8: U13.M6@1086.42,1679.53 v3(1106.1,1679.53)
  LYR4 w5.25: v3(1106.1,1679.53) 1153.13,1632.5 1327.5,1632.5 1385,1690 1385,1745 1520,1880 1735,1880 1775,1920 P8.21@1775,1975
  BOTTOM w4.75: R110.2@1775,1870 P8.21@1775,1975
MMC1_CMD: P8.20 R109.2 U5.V9 U13.M5 | length 1715.1
  TOP w4.75: P8.20@1675,2075 1725,2025 1725,1950 1795,1880 1795,1560 1827.74,1527.26 1827.74,1446.69 1815.75,1434.7 U5.V9@1815.75,1417.72
  TOP w8: U13.M5@1086.42,1699.21 v3(1106.1,1699.21)
  LYR4 w5.25: v3(1106.1,1699.21) 1158.46,1646.85 1321.85,1646.85 1370,1695 1370,1750 1520,1900 v1(1675,1900)
  BOTTOM w4.75: R109.2@1675,1870 v1(1675,1900) 1630,1945 1630,2030 P8.20@1675,2075
MMC1_DAT0: P8.25 R101.2 U5.U7 U13.A3 | length 1347.6
  TOP w4.75: U13.A3@1302.95,1738.58 1468.58,1738.58 v1(1500,1770) ; U5.U7@1878.74,1386.22 1894.47,1401.95 1894.47,1434.47 1900,1440 1900,1517.5 1905,1522.5 1905,1880 v1(1925,1900)
  LYR4 w5.25: v1(1500,1770) 1555,1770 1625,1840 1865,1840 v1(1925,1900)
  BOTTOM w4.75: R101.2@1925,1870 v1(1925,1900) 1925,1925 P8.25@1975,1975
MMC1_DAT1: P8.24 R102.2 U5.V7 U13.A4 | length 1536.3
  TOP w4.75: U13.A4@1302.95,1718.9 1478.9,1718.9 1525,1765 v1(1525,1800) ; P8.24@1875,2075 1920,2030 1920,1945 1895,1920 1895,1534.26 1890,1529.26 1890,1445 1878.74,1433.74 U5.V7@1878.74,1417.72
  LYR4 w5.25: v1(1525,1800) 1585,1860 1785,1860 v1(1825,1900)
  BOTTOM w4.75: R102.2@1825,1870 v1(1825,1900) 1825,2025 P8.24@1875,2075
MMC1_DAT2: P8.5 R103.2 U5.R8 U13.A5 | length 1373.2
  TOP w4.75: U5.R8@1847.24,1323.23 v1(1862.99,1338.98)
  TOP w8: U13.A5@1302.95,1699.21 v3(1325,1699.21)
  LYR3 w4.75: 1847.24,1380 1847.24,1354.73 v1(1862.99,1338.98)
  LYR3 w5.25: v3(1325,1699.21) 1345.79,1720 1620,1720 1820,1520 1820,1410 1847.24,1382.76 1847.24,1380
  LYR4 w5.25: v1(1025,1900) 1025,1885 1090,1820 1145,1820 1270,1695 1270,1685 1280,1675 1300.79,1675 v3(1325,1699.21)
  BOTTOM w4.75: P8.5@975,1975 1025,1925 v1(1025,1900) R103.2@1025,1870
MMC1_DAT3: P8.6 R104.2 U5.T8 U13.B2 | length 1364.1
  TOP w4.75: U13.B2@1283.27,1758.27 v3(1293.11,1768.11) ; U5.T8@1847.24,1354.72 v1(1862.99,1370.47)
  LYR3 w5.25: v3(1293.11,1768.11) 1326.22,1735 1625,1735 1830.25,1529.75 1830.25,1419.75 1862.99,1387.01 v1(1862.99,1370.47)
  LYR4 w5.25: v1(1075,1900) 1110,1865 1196.22,1865 v3(1293.11,1768.11)
  BOTTOM w4.75: P8.6@975,2075 1025,2025 1025,1950 v1(1075,1900) R104.2@1075,1870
